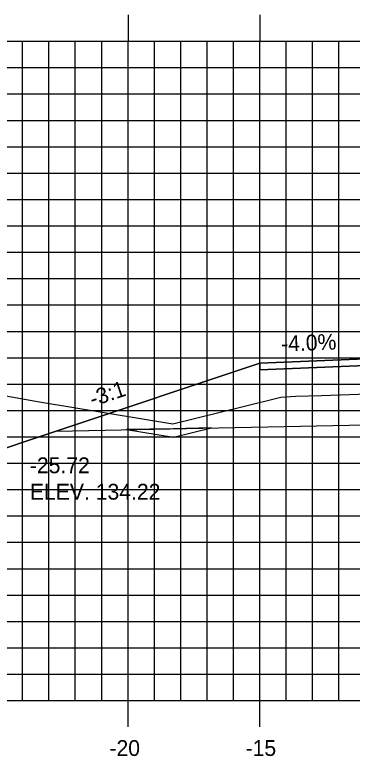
# Model space of a CAD drawing. Extents: x 1146525 to 1146695, y 608981 to 609091.
# Drawn here: x 1146583.38 to 1146596.17, y 609018.23 to 609046.34 of the extents above; entities that cross this region are included whole.
import ezdxf

# ---------------------------------------------------------------- set-up
doc = ezdxf.new("R2010")
doc.units = 0
for name, color, linetype in [('ANNOTATION', 7, 'Continuous'), ('D_Roadway_Edge_Shoulder', 7, 'Continuous'), ('D_Roadway_SlopeLines', 7, 'Continuous'), ('D_Roadway_SubGrade', 7, 'Continuous'), ('D_Text_Standard', 7, 'Continuous'), ('H_V ANNOTATION', 7, 'Continuous'), ('MAJOR', 7, 'Continuous'), ('MINOR', 7, 'Continuous'), ('S_Roadway_Centerline', 7, 'Continuous'), ('SHADING', 7, 'Continuous')]:
    doc.layers.add(name, color=color, linetype=linetype)

msp = doc.modelspace()

# ---------------------------------------------------------------- linework, layer by layer
msp.add_lwpolyline([(1146573.905, 609032.428), (1146575.155, 609032.306), (1146576.405, 609032.04), (1146577.655, 609031.631), (1146578.905, 609031.077), (1146581.947, 609029.556), (1146584.947, 609030.556), (1146592.67, 609033.131), (1146592.671, 609033.131), (1146596.671, 609033.291), (1146607.671, 609033.511), (1146618.671, 609033.291), (1146622.671, 609033.131), (1146630.395, 609030.556), (1146633.395, 609029.556), (1146642.977, 609034.348), (1146644.227, 609034.902), (1146645.477, 609035.313), (1146646.727, 609035.583), (1146647.977, 609035.71)])
at = {"layer": 'D_Roadway_Edge_Shoulder'}
msp.add_lwpolyline([(1146596.671, 609033.291), (1146592.671, 609033.131), (1146592.671, 609032.881), (1146596.671, 609033.041)], close=True, dxfattribs=at)
at = {"layer": 'D_Roadway_SlopeLines'}
msp.add_lwpolyline([(1146584.947, 609030.556), (1146581.947, 609029.556)], dxfattribs=at)
at = {"layer": 'D_Roadway_SubGrade'}
msp.add_lwpolyline([(1146596.671, 609032.874), (1146596.671, 609033.041), (1146592.671, 609032.881), (1146592.671, 609033.131), (1146592.67, 609033.131), (1146584.947, 609030.556), (1146596.671, 609030.791)], close=True, dxfattribs=at)
msp.add_lwpolyline([(1146587.61, 609030.61), (1146589.394, 609030.317), (1146590.838, 609030.674)], dxfattribs=at)
msp.add_lwpolyline([(1146587.61, 609030.61), (1146589.394, 609030.317), (1146590.838, 609030.674)], dxfattribs=at)
at = {"layer": 'MAJOR'}
for p, q in [((1146587.671, 609046.337), (1146587.671, 609045.335)), ((1146592.671, 609046.337), (1146592.671, 609045.335)), ((1146537.671, 609045.335), (1146677.671, 609045.335)), ((1146537.671, 609045.335), (1146677.671, 609045.335)), ((1146587.671, 609020.335), (1146587.671, 609045.335)), ((1146592.671, 609020.335), (1146592.671, 609045.335)), ((1146537.671, 609040.335), (1146677.671, 609040.335)), ((1146537.671, 609035.335), (1146677.671, 609035.335)), ((1146537.671, 609030.335), (1146677.671, 609030.335)), ((1146537.671, 609025.335), (1146677.671, 609025.335)), ((1146537.671, 609020.335), (1146677.671, 609020.335)), ((1146537.671, 609020.335), (1146677.671, 609020.335)), ((1146587.671, 609019.333), (1146587.671, 609020.335)), ((1146592.671, 609019.333), (1146592.671, 609020.335))]:
    msp.add_line(p, q, dxfattribs=at)
at = {"layer": 'MINOR'}
for p, q in [((1146583.671, 609020.335), (1146583.671, 609045.335)), ((1146584.671, 609020.335), (1146584.671, 609045.335)), ((1146585.671, 609020.335), (1146585.671, 609045.335)), ((1146586.671, 609020.335), (1146586.671, 609045.335)), ((1146588.671, 609020.335), (1146588.671, 609045.335)), ((1146589.671, 609020.335), (1146589.671, 609045.335)), ((1146590.671, 609020.335), (1146590.671, 609045.335)), ((1146591.671, 609020.335), (1146591.671, 609045.335)), ((1146593.671, 609020.335), (1146593.671, 609045.335)), ((1146594.671, 609020.335), (1146594.671, 609045.335)), ((1146595.671, 609020.335), (1146595.671, 609045.335)), ((1146537.671, 609044.335), (1146677.671, 609044.335)), ((1146537.671, 609043.335), (1146677.671, 609043.335)), ((1146537.671, 609042.335), (1146677.671, 609042.335)), ((1146537.671, 609041.335), (1146677.671, 609041.335)), ((1146537.671, 609039.335), (1146677.671, 609039.335)), ((1146537.671, 609038.335), (1146677.671, 609038.335)), ((1146537.671, 609037.335), (1146677.671, 609037.335)), ((1146537.671, 609036.335), (1146677.671, 609036.335)), ((1146537.671, 609034.335), (1146677.671, 609034.335)), ((1146537.671, 609033.335), (1146677.671, 609033.335)), ((1146537.671, 609032.335), (1146677.671, 609032.335)), ((1146537.671, 609031.335), (1146677.671, 609031.335)), ((1146537.671, 609029.335), (1146677.671, 609029.335)), ((1146537.671, 609028.335), (1146677.671, 609028.335)), ((1146537.671, 609027.335), (1146677.671, 609027.335)), ((1146537.671, 609026.335), (1146677.671, 609026.335)), ((1146537.671, 609024.335), (1146677.671, 609024.335)), ((1146537.671, 609023.335), (1146677.671, 609023.335)), ((1146537.671, 609022.335), (1146677.671, 609022.335)), ((1146537.671, 609021.335), (1146677.671, 609021.335))]:
    msp.add_line(p, q, dxfattribs=at)
at = {"layer": 'S_Roadway_Centerline'}
msp.add_lwpolyline([(1146557.189, 609033.149), (1146565.05, 609032.785), (1146581.825, 609032.109), (1146584.311, 609031.657), (1146589.374, 609030.827), (1146592.033, 609031.484), (1146593.468, 609031.837), (1146594.03, 609031.88), (1146595.014, 609031.905), (1146600.278, 609032.092), (1146606.448, 609032.182), (1146612.282, 609032.042), (1146617.286, 609031.872), (1146619.517, 609031.64), (1146621.574, 609031.449), (1146622.756, 609030.931), (1146624.182, 609030.468), (1146629.549, 609032.75), (1146635.043, 609035.129), (1146648.103, 609035.716), (1146654.911, 609035.417)], dxfattribs=at)
at = {"layer": 'SHADING'}
for p, q in [((1146590.838, 609030.674), (1146589.378, 609030.645)), ((1146589.378, 609030.645), (1146587.61, 609030.61))]:
    msp.add_line(p, q, dxfattribs=at)
msp.add_lwpolyline([(1146587.61, 609030.61), (1146589.394, 609030.317), (1146590.838, 609030.674)], dxfattribs=at)

# ---------------------------------------------------------------- texts
at = {"layer": 'ANNOTATION'}
for s, rotation, p in [('-4.0%', 2.2906, (1146593.487, 609033.564)), ('-3:1', 18.4348, (1146586.326, 609031.47))]:
    msp.add_text(s, height=0.6, rotation=rotation, dxfattribs=at).set_placement(p)
at = {"layer": 'D_Text_Standard'}
for s, p in [('-25.72', (1146583.947, 609028.956)), ('ELEV. 134.22', (1146583.947, 609027.954))]:
    msp.add_text(s, height=0.6, dxfattribs=at).set_placement(p)
at = {"layer": 'H_V ANNOTATION'}
for s, p in [('-20', (1146586.965, 609018.235)), ('-15', (1146592.128, 609018.235))]:
    msp.add_text(s, height=0.6, dxfattribs=at).set_placement(p)

doc.saveas('drawing.dxf')
